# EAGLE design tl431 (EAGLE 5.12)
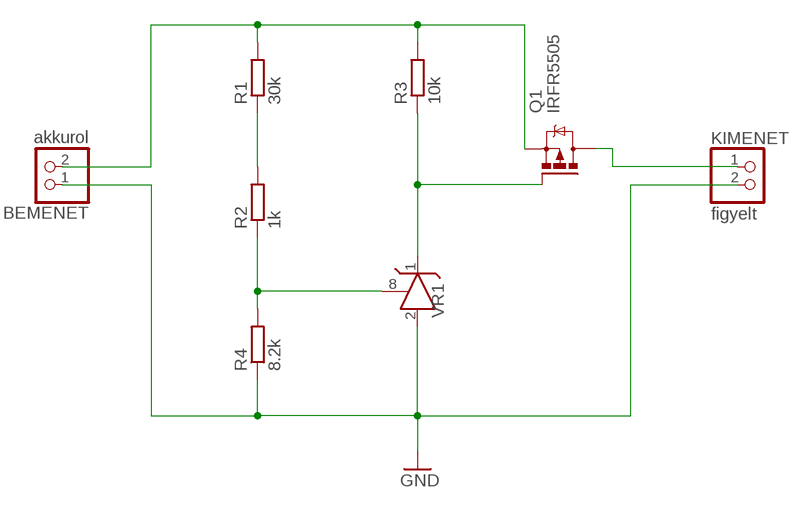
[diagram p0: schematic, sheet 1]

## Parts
BEMENET  akkurol  PINHD-1X2  [1X02]
KIMENET  figyelt  PINHD-1X2  [1X02]
Q1  IRFR5505  IRFR5305  [D-PAK_TO252AA]
R1  30k  R-EU_R0805  [R0805]
R2  1k  R-EU_R0805  [R0805]
R3  10k  R-EU_R0805  [R0805]
R4  8.2k  R-EU_R0805  [R0805]
VR1  TL431CLPSO-8  [SOIC8]

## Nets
GND: BEMENET.1 KIMENET.2 R4.1 VR1.2(A$0)
N$1: R2.1 R4.2 VR1.8(R)
N$2: R1.1 R2.2
N$3: Q1.1(G) R3.1 VR1.1(C)
N$4: BEMENET.2 Q1.3(S) R1.2 R3.2
N$8: KIMENET.1 Q1.4(D)
Unconnected: VR1.3(A$1) VR1.6(A$2) VR1.7(A$3)

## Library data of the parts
BEMENET KIMENET = pinhead:PINHD-1X2: PIN HEADER
Q1 = transistor-power:IRF?5305: HEXFET Power MOSFET Source: http://www.irf.com/product-info/datasheets/data/irfr5305pbf.pdf
R1-R4 = rcl:R-EU_: RESISTOR, European symbol
VR1 = sajat:TL431CLP: VOLTAGE REGULATOR

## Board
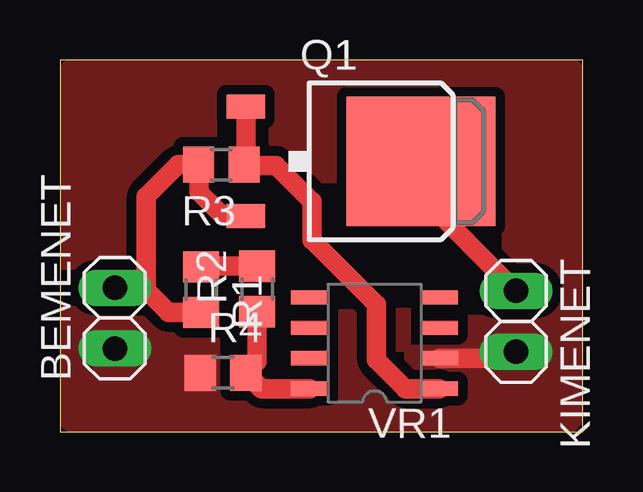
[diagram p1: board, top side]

Size 21.8 x 15.5 mm. Coordinates in mm from the lower left corner, seen from the top.
Outline: 0,0 21.8,0 21.8,15.5 0,15.5 0,0
Copper layers (1*16): Top 0.035mm / dielectric 1.5mm / Bottom 0.035mm
Design rules "default *": minimum track width 10mil, minimum drill 24mil, track to track 8mil, track to pad 8mil, pad to pad 8mil, via to via 8mil, smd to smd 8mil, copper to edge 0mil, drill to drill 8mil, minimum pad ring 10mil, minimum via ring 8mil, stop-mask expansion 4mil, vias tented up to drill 0mil, thermal gap 10mil

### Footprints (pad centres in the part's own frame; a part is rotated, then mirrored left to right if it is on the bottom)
1X02 = drill 1.016 long: 1 -1.27,0; 2 1.27,0
D-PAK_TO252AA = smd 1 x 1.6: 1 -2.28,-4.8; 3 2.28,-4.8 | smd 5.4 x 6.2: 4 0,2.5
R0805 = smd 1.3 x 1.5: 1 -0.95,0; 2 0.95,0
SOIC8 = smd 1.55 x 0.6: 1 -2.7,1.905; 2 -2.7,0.635; 3 -2.7,-0.635; 4 -2.7,-1.905; 5 2.7,-1.905; 6 2.7,-0.635; 7 2.7,0.635; 8 2.7,1.905

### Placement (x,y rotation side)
BEMENET  2.29,4.73 90 top
KIMENET  19.02,4.6 270 top
Q1  12.55,11.27 270 top
R1  5.89,5.92 270 top
R2  8.22,5.95 90 top
R3  6.73,11.13 180 top
R4  6.8,2.45 0 top
VR1  13.12,3.69 180 top

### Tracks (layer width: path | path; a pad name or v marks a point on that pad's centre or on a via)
GND
  Top 0.813: VR1.2 18.75,3.06 KIMENET.2
  pour Top (isolate 0.406, no thermals): 21.3,0.4 0.4,0.4 0.4,15.1 21.4,15.1 21.4,0.6
N$1
  Top 0.813: R2.1 8.22,2.92 R4.2 8.41,1.78 VR1.8
N$2
  Top 0.813: R2.2 5.92,6.9 R1.1
N$3
  Top 0.813: VR1.1 14.41,1.78 13.2,3 13.2,5.3 10.5,8 10.5,9.6 9,11.1 7.71,11.1 R3.1 7.75,11.2 Q1.1
N$4
  Top 0.813: Q1.3 6.81,8.99 5.8,10 5.8,11.11 R3.2 4.93,11.13 3.6,9.8 3.6,5.9 | R1.2 4.53,4.97 3.6,5.9 | 3.6,5.9 2.39,5.9 BEMENET.2
N$8
  Top 0.813: Q1.4 15.05,9.84 KIMENET.1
